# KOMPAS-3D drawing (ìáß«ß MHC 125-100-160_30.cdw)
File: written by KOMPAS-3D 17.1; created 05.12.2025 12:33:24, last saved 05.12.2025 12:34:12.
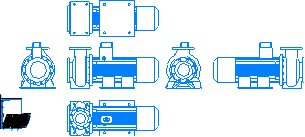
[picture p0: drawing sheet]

Sheet 1: A4, portrait

Title block, sheet 1: name: Насос MHC / 125-100-160_30; material: Сталь 10  ГОСТ 1050-88; mass: 326,95; sheets: 1; sheet format: A4

Views: Вид 1, Спереди, Проекционный вид 2, Проекционный вид 3, Проекционный вид 4, Проекционный вид 5, Проекционный вид 6
Referenced files in \\adlc.lan\data\АДЛ_ПКД\3D-модели\ADL production\Насосы ГРАНПАМП\Насосы ГРАНПАМП серии МНС\KOMPAS 3D\: Насос MHC 125-100-160_30.m3d
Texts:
  Andrey
  АДЛ
Dimensions and other numbers on the sheet: 1:1; 1; 125-100-160_30; 326,95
